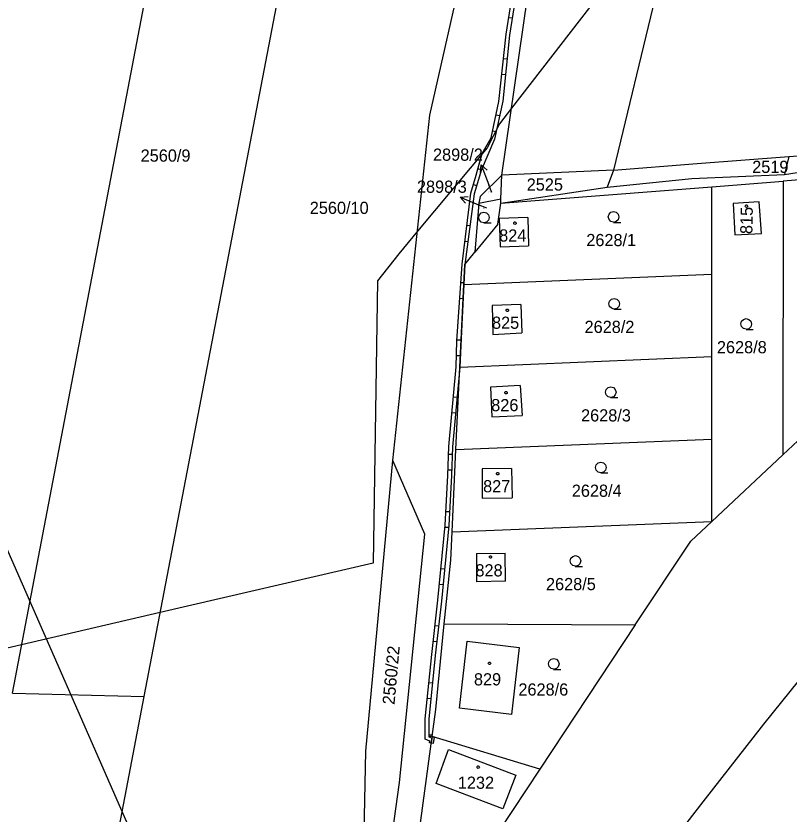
# Model space of a CAD drawing. Extents: x -760611 to -758411, y -1176479 to -1174807.
# Drawn here: x -759476.2 to -759368.4, y -1175293 to -1175181.7 of the extents above; entities that cross this region are included whole.
import ezdxf

# ---------------------------------------------------------------- set-up
doc = ezdxf.new("R2010")
doc.units = 0
for name, color, linetype in [('1', 7, 'Continuous'), ('11', 7, 'Continuous'), ('12', 7, 'Continuous'), ('13', 7, 'Continuous'), ('2', 7, 'Continuous'), ('3', 7, 'Continuous'), ('5', 7, 'Continuous'), ('6', 7, 'Continuous'), ('7', 7, 'Continuous')]:
    doc.layers.add(name, color=color, linetype=linetype)

msp = doc.modelspace()

# ---------------------------------------------------------------- linework, layer by layer
at = {"layer": '1'}
for p, q in [((-759370.78, -1175111.37), (-759392.87, -1175203.23)), ((-759458.35, -1175276.62), (-759430.62, -1175131.87)), ((-759476.73, -1175276.15), (-759451.36, -1175143.73)), ((-759408.44, -1175203.92), (-759400.15, -1175145.98)), ((-759418.48, -1175195.58), (-759410.58, -1175160.57)), ((-759423.64, -1175243.71), (-759418.48, -1175195.58)), ((-759369.05, -1175203.82), (-759338.17, -1175199.04)), ((-759368.43, -1175201.33), (-759365.05, -1175201.07)), ((-759381.2, -1175202.32), (-759368.43, -1175201.33)), ((-759368.43, -1175201.33), (-759369.05, -1175203.82)), ((-759392.87, -1175203.23), (-759408.44, -1175203.92)), ((-759392.87, -1175203.23), (-759393.78, -1175205.6)), ((-759392.87, -1175203.23), (-759381.2, -1175202.32)), ((-759408.44, -1175203.92), (-759411.49, -1175206.9)), ((-759408.58, -1175207.25), (-759408.44, -1175203.92)), ((-759393.78, -1175205.6), (-759381.97, -1175204.4)), ((-759381.97, -1175204.4), (-759369.05, -1175203.82)), ((-759357.27, -1175203.83), (-759369.21, -1175204.76)), ((-759408.6, -1175207.83), (-759379.17, -1175205.54)), ((-759379.17, -1175205.54), (-759369.21, -1175204.76)), ((-759379.17, -1175217.73), (-759379.17, -1175205.54)), ((-759369.21, -1175204.76), (-759369.26, -1175242.94)), ((-759408.6, -1175207.83), (-759393.78, -1175205.6)), ((-759411.49, -1175206.9), (-759411.65, -1175207.82)), ((-759411.65, -1175207.82), (-759408.58, -1175207.25)), ((-759408.6, -1175207.83), (-759408.58, -1175207.25)), ((-759372.56, -1175207.63), (-759376.17, -1175207.89)), ((-759372.24, -1175212.08), (-759372.56, -1175207.63)), ((-759411.65, -1175207.82), (-759412.21, -1175214.67)), ((-759409, -1175210.75), (-759408.6, -1175207.83)), ((-759376.17, -1175207.89), (-759375.96, -1175212.24)), ((-759404.85, -1175209.84), (-759408.82, -1175209.97)), ((-759408.82, -1175209.97), (-759408.68, -1175213.93)), ((-759404.85, -1175209.84), (-759404.72, -1175213.8)), ((-759409, -1175210.75), (-759412.21, -1175214.67)), ((-759375.96, -1175212.24), (-759372.24, -1175212.08)), ((-759408.68, -1175213.93), (-759404.72, -1175213.8)), ((-759413.64, -1175216.41), (-759412.21, -1175214.67)), ((-759413.77, -1175219.2), (-759413.64, -1175216.41)), ((-759413.77, -1175219.2), (-759379.17, -1175217.73)), ((-759379.18, -1175229.23), (-759379.17, -1175217.73)), ((-759414.32, -1175230.69), (-759413.77, -1175219.2)), ((-759405.83, -1175221.97), (-759409.79, -1175222.12)), ((-759409.79, -1175222.12), (-759409.71, -1175226.13)), ((-759405.83, -1175221.97), (-759405.68, -1175225.92)), ((-759409.71, -1175226.13), (-759405.68, -1175225.92)), ((-759414.32, -1175230.69), (-759379.18, -1175229.23)), ((-759379.18, -1175240.73), (-759379.18, -1175229.23)), ((-759414.86, -1175242.17), (-759414.32, -1175230.69)), ((-759357.28, -1175231.73), (-759369.26, -1175242.94)), ((-759405.89, -1175233.26), (-759410.05, -1175233.52)), ((-759405.89, -1175233.26), (-759405.64, -1175237.45)), ((-759410.05, -1175233.52), (-759409.87, -1175237.65)), ((-759409.87, -1175237.65), (-759405.64, -1175237.45)), ((-759414.86, -1175242.17), (-759379.18, -1175240.73)), ((-759379.19, -1175252.23), (-759379.18, -1175240.73)), ((-759415.4, -1175253.65), (-759414.86, -1175242.17)), ((-759369.26, -1175242.94), (-759379.19, -1175252.23)), ((-759427.43, -1175284.24), (-759423.64, -1175243.71)), ((-759419.22, -1175253.98), (-759423.64, -1175243.71)), ((-759407.11, -1175244.83), (-759411.22, -1175244.91)), ((-759411.22, -1175244.91), (-759411.21, -1175248.99)), ((-759407.11, -1175244.83), (-759407.02, -1175248.91)), ((-759411.21, -1175248.99), (-759407.02, -1175248.91)), ((-759415.4, -1175253.65), (-759379.19, -1175252.23)), ((-759379.19, -1175252.23), (-759382.11, -1175254.96)), ((-759422.71, -1175288.64), (-759419.22, -1175253.98)), ((-759415.59, -1175257.64), (-759415.4, -1175253.65)), ((-759389.84, -1175266.63), (-759382.11, -1175254.96)), ((-759411.98, -1175256.7), (-759412, -1175260.63)), ((-759411.98, -1175256.7), (-759407.99, -1175256.65)), ((-759407.97, -1175260.54), (-759407.99, -1175256.65)), ((-759416.48, -1175266.49), (-759415.59, -1175257.64)), ((-759407.97, -1175260.54), (-759412, -1175260.63)), ((-759417.68, -1175278.43), (-759416.48, -1175266.49)), ((-759416.48, -1175266.49), (-759389.84, -1175266.63)), ((-759389.84, -1175266.63), (-759403.18, -1175286.77)), ((-759414.38, -1175278.27), (-759413.28, -1175268.93)), ((-759413.28, -1175268.93), (-759406.02, -1175269.81)), ((-759406.02, -1175269.81), (-759407.12, -1175279.13)), ((-759476.73, -1175276.15), (-759458.35, -1175276.62)), ((-759463.25, -1175302.25), (-759458.35, -1175276.62)), ((-759418.19, -1175282.22), (-759417.68, -1175278.43)), ((-759407.12, -1175279.13), (-759414.38, -1175278.27)), ((-759422.12, -1175311.42), (-759418.19, -1175282.22)), ((-759403.18, -1175286.77), (-759418.19, -1175282.22)), ((-759427.83, -1175303.15), (-759427.43, -1175284.24)), ((-759417.64, -1175288.75), (-759415.88, -1175284.03)), ((-759415.88, -1175284.03), (-759406.51, -1175287.61)), ((-759403.18, -1175286.77), (-759408.89, -1175295.4)), ((-759406.51, -1175287.61), (-759408.32, -1175292.3)), ((-759424.83, -1175303.24), (-759422.71, -1175288.64)), ((-759408.32, -1175292.3), (-759417.64, -1175288.75))]:
    msp.add_line(p, q, dxfattribs=at)
at = {"layer": '11'}
msp.add_lwpolyline([(-759387.91, -1175169.78), (-759407.11, -1175194.59), (-759408.78, -1175196.76), (-759410.49, -1175200.14), (-759420.21, -1175211.75), (-759422.84, -1175214.88), (-759425.82, -1175218.68), (-759426.39, -1175258.03), (-759456.11, -1175264.92), (-759475.44, -1175269.41), (-759487.07, -1175272.11)], dxfattribs=at)
at = {"layer": '12'}
for p, q in [((-759372.56, -1175207.63), (-759376.17, -1175207.89)), ((-759372.24, -1175212.08), (-759372.56, -1175207.63)), ((-759376.17, -1175207.89), (-759375.96, -1175212.24)), ((-759404.85, -1175209.84), (-759408.82, -1175209.97)), ((-759408.82, -1175209.97), (-759408.68, -1175213.93)), ((-759404.85, -1175209.84), (-759404.72, -1175213.8)), ((-759375.96, -1175212.24), (-759372.24, -1175212.08)), ((-759408.68, -1175213.93), (-759404.72, -1175213.8)), ((-759405.83, -1175221.97), (-759409.79, -1175222.12)), ((-759409.79, -1175222.12), (-759409.71, -1175226.13)), ((-759405.83, -1175221.97), (-759405.68, -1175225.92)), ((-759409.71, -1175226.13), (-759405.68, -1175225.92)), ((-759405.89, -1175233.26), (-759410.05, -1175233.52)), ((-759405.89, -1175233.26), (-759405.64, -1175237.45)), ((-759410.05, -1175233.52), (-759409.87, -1175237.65)), ((-759409.87, -1175237.65), (-759405.64, -1175237.45)), ((-759407.11, -1175244.83), (-759411.22, -1175244.91)), ((-759411.22, -1175244.91), (-759411.21, -1175248.99)), ((-759407.11, -1175244.83), (-759407.02, -1175248.91)), ((-759411.21, -1175248.99), (-759407.02, -1175248.91)), ((-759411.98, -1175256.7), (-759412, -1175260.63)), ((-759411.98, -1175256.7), (-759407.99, -1175256.65)), ((-759407.97, -1175260.54), (-759407.99, -1175256.65)), ((-759407.97, -1175260.54), (-759412, -1175260.63)), ((-759414.38, -1175278.27), (-759413.28, -1175268.93)), ((-759413.28, -1175268.93), (-759406.02, -1175269.81)), ((-759406.02, -1175269.81), (-759407.12, -1175279.13)), ((-759407.12, -1175279.13), (-759414.38, -1175278.27)), ((-759417.64, -1175288.75), (-759415.88, -1175284.03)), ((-759415.88, -1175284.03), (-759406.51, -1175287.61)), ((-759406.51, -1175287.61), (-759408.32, -1175292.3)), ((-759408.32, -1175292.3), (-759417.64, -1175288.75))]:
    msp.add_line(p, q, dxfattribs=at)
at = {"layer": '13'}
for p, q in [((-759407.5, -1175181.92), (-759407, -1175182)), ((-759407.72, -1175187.74), (-759408.22, -1175187.69)), ((-759408.46, -1175189.86), (-759407.96, -1175189.91)), ((-759408.78, -1175195.66), (-759409.27, -1175195.55)), ((-759409.75, -1175197.74), (-759409.26, -1175197.85)), ((-759411.33, -1175203.2), (-759411.81, -1175203.07)), ((-759412.44, -1175205.22), (-759411.96, -1175205.36)), ((-759412.91, -1175211.02), (-759413.41, -1175210.96)), ((-759413.59, -1175213.12), (-759413.1, -1175213.18)), ((-759413.76, -1175218.97), (-759414.26, -1175218.95)), ((-759414.31, -1175221.09), (-759413.81, -1175221.12)), ((-759414.14, -1175226.96), (-759414.64, -1175226.94)), ((-759414.78, -1175229.07), (-759414.28, -1175229.09)), ((-759414.71, -1175234.94), (-759415.21, -1175234.89)), ((-759415.41, -1175237.05), (-759414.92, -1175237.09)), ((-759415.38, -1175242.91), (-759415.88, -1175242.9)), ((-759415.95, -1175245.02), (-759415.45, -1175245.04)), ((-759415.76, -1175250.9), (-759416.26, -1175250.87)), ((-759416.39, -1175253.01), (-759415.89, -1175253.04)), ((-759416.46, -1175258.87), (-759416.95, -1175258.82)), ((-759417.16, -1175260.97), (-759416.66, -1175261.02)), ((-759417.28, -1175266.83), (-759417.78, -1175266.77)), ((-759418.03, -1175268.93), (-759417.53, -1175268.98)), ((-759418.15, -1175274.78), (-759418.64, -1175274.73)), ((-759418.87, -1175276.88), (-759418.37, -1175276.93)), ((-759418.17, -1175282.03), (-759418.66, -1175281.97)), ((-759418.31, -1175283.14), (-759418.19, -1175282.22)), ((-759418.19, -1175282.22), (-759417.91, -1175282.3)), ((-759417.91, -1175282.3), (-759418.03, -1175283.18)), ((-759418.03, -1175283.18), (-759418.31, -1175283.14))]:
    msp.add_line(p, q, dxfattribs=at)
msp.add_lwpolyline([(-759405.3, -1175171.21), (-759407.37, -1175184.4), (-759408.34, -1175193.63), (-759409.5, -1175198.93), (-759411.36, -1175203.3), (-759411.58, -1175204.08), (-759412.3, -1175206.53), (-759413.64, -1175216.41), (-759414.04, -1175224.78), (-759414.32, -1175230.69), (-759415.35, -1175241.84), (-759415.47, -1175245.82), (-759415.87, -1175252.8), (-759416.89, -1175263.35), (-759417.75, -1175270.92), (-759418.66, -1175279.8), (-759418.63, -1175282.26), (-759418.42, -1175282.35), (-759418.39, -1175282.12), (-759418.19, -1175282.22), (-759418.31, -1175283.14), (-759418.53, -1175283.11), (-759418.5, -1175282.87), (-759419.13, -1175282.6), (-759419.16, -1175279.75), (-759418.24, -1175270.77), (-759417.37, -1175263.19), (-759416.37, -1175252.74), (-759415.97, -1175245.8), (-759415.85, -1175241.76), (-759414.82, -1175230.64), (-759414.73, -1175227.02), (-759413.98, -1175216.36), (-759412.8, -1175206.45), (-759412.06, -1175203.94), (-759411.86, -1175203.24), (-759411.18, -1175200.92), (-759409.96, -1175198.71), (-759408.86, -1175193.67), (-759407.87, -1175184.28), (-759405.78, -1175171.03)], dxfattribs=at)
at = {"layer": '3'}
for points in [[(-759410.94, -1175210.58), (-759411.32, -1175210.48), (-759411.59, -1175210.21), (-759411.69, -1175209.84), (-759411.59, -1175209.47), (-759411.32, -1175209.2), (-759410.95, -1175209.1), (-759410.58, -1175209.2), (-759410.31, -1175209.47), (-759410.21, -1175209.85), (-759410.31, -1175210.23), (-759410.58, -1175210.5), (-759410.96, -1175210.6), (-759409.96, -1175210.6)], [(-759392.86, -1175210.49), (-759393.24, -1175210.39), (-759393.51, -1175210.12), (-759393.61, -1175209.75), (-759393.51, -1175209.38), (-759393.24, -1175209.11), (-759392.87, -1175209.01), (-759392.5, -1175209.11), (-759392.23, -1175209.38), (-759392.13, -1175209.76), (-759392.23, -1175210.14), (-759392.5, -1175210.41), (-759392.88, -1175210.51), (-759391.88, -1175210.51)], [(-759392.78, -1175222.6), (-759393.16, -1175222.5), (-759393.43, -1175222.23), (-759393.53, -1175221.86), (-759393.43, -1175221.49), (-759393.16, -1175221.22), (-759392.79, -1175221.12), (-759392.42, -1175221.22), (-759392.15, -1175221.49), (-759392.05, -1175221.87), (-759392.15, -1175222.25), (-759392.42, -1175222.52), (-759392.8, -1175222.62), (-759391.8, -1175222.62)], [(-759374.37, -1175225.42), (-759374.75, -1175225.32), (-759375.02, -1175225.05), (-759375.12, -1175224.68), (-759375.02, -1175224.31), (-759374.75, -1175224.04), (-759374.38, -1175223.94), (-759374.01, -1175224.04), (-759373.74, -1175224.31), (-759373.64, -1175224.69), (-759373.74, -1175225.07), (-759374.01, -1175225.34), (-759374.39, -1175225.44), (-759373.39, -1175225.44)], [(-759393.26, -1175234.93), (-759393.64, -1175234.83), (-759393.91, -1175234.56), (-759394.01, -1175234.19), (-759393.91, -1175233.82), (-759393.64, -1175233.55), (-759393.27, -1175233.45), (-759392.9, -1175233.55), (-759392.63, -1175233.82), (-759392.53, -1175234.2), (-759392.63, -1175234.58), (-759392.9, -1175234.85), (-759393.28, -1175234.95), (-759392.28, -1175234.95)], [(-759394.64, -1175245.44), (-759395.02, -1175245.34), (-759395.29, -1175245.07), (-759395.39, -1175244.7), (-759395.29, -1175244.33), (-759395.02, -1175244.06), (-759394.65, -1175243.96), (-759394.28, -1175244.06), (-759394.01, -1175244.33), (-759393.91, -1175244.71), (-759394.01, -1175245.09), (-759394.28, -1175245.36), (-759394.66, -1175245.46), (-759393.66, -1175245.46)], [(-759398.19, -1175258.47), (-759398.57, -1175258.37), (-759398.84, -1175258.1), (-759398.94, -1175257.73), (-759398.84, -1175257.36), (-759398.57, -1175257.09), (-759398.2, -1175256.99), (-759397.83, -1175257.09), (-759397.56, -1175257.36), (-759397.46, -1175257.74), (-759397.56, -1175258.12), (-759397.83, -1175258.39), (-759398.21, -1175258.49), (-759397.21, -1175258.49)], [(-759401.21, -1175272.83), (-759401.59, -1175272.73), (-759401.86, -1175272.46), (-759401.96, -1175272.09), (-759401.86, -1175271.72), (-759401.59, -1175271.45), (-759401.22, -1175271.35), (-759400.85, -1175271.45), (-759400.58, -1175271.72), (-759400.48, -1175272.1), (-759400.58, -1175272.48), (-759400.85, -1175272.75), (-759401.23, -1175272.85), (-759400.23, -1175272.85)]]:
    msp.add_lwpolyline(points, dxfattribs=at)
at = {"layer": '5'}
for points in [[(-759374.34, -1175208.08), (-759374.24, -1175208.1), (-759374.19, -1175208.19), (-759374.17, -1175208.25), (-759374.19, -1175208.34), (-759374.27, -1175208.41), (-759374.34, -1175208.42), (-759374.43, -1175208.39), (-759374.49, -1175208.33), (-759374.51, -1175208.25), (-759374.49, -1175208.16), (-759374.41, -1175208.09)], [(-759406.63, -1175210.45), (-759406.53, -1175210.47), (-759406.48, -1175210.56), (-759406.46, -1175210.62), (-759406.48, -1175210.71), (-759406.56, -1175210.78), (-759406.63, -1175210.79), (-759406.72, -1175210.76), (-759406.78, -1175210.7), (-759406.8, -1175210.62), (-759406.78, -1175210.53), (-759406.7, -1175210.46)], [(-759407.7, -1175222.6), (-759407.6, -1175222.62), (-759407.55, -1175222.71), (-759407.53, -1175222.77), (-759407.55, -1175222.86), (-759407.63, -1175222.93), (-759407.7, -1175222.94), (-759407.79, -1175222.91), (-759407.85, -1175222.85), (-759407.87, -1175222.77), (-759407.85, -1175222.68), (-759407.77, -1175222.61)], [(-759407.87, -1175234.1), (-759407.77, -1175234.12), (-759407.72, -1175234.21), (-759407.7, -1175234.27), (-759407.72, -1175234.36), (-759407.8, -1175234.43), (-759407.87, -1175234.44), (-759407.96, -1175234.41), (-759408.02, -1175234.35), (-759408.04, -1175234.27), (-759408.02, -1175234.18), (-759407.94, -1175234.11)], [(-759409.03, -1175245.4), (-759408.93, -1175245.42), (-759408.88, -1175245.51), (-759408.86, -1175245.57), (-759408.88, -1175245.66), (-759408.96, -1175245.73), (-759409.03, -1175245.74), (-759409.12, -1175245.71), (-759409.18, -1175245.65), (-759409.2, -1175245.57), (-759409.18, -1175245.48), (-759409.1, -1175245.41)], [(-759410.05, -1175257.01), (-759409.95, -1175257.03), (-759409.9, -1175257.12), (-759409.88, -1175257.18), (-759409.9, -1175257.27), (-759409.98, -1175257.34), (-759410.05, -1175257.35), (-759410.14, -1175257.32), (-759410.2, -1175257.26), (-759410.22, -1175257.18), (-759410.2, -1175257.09), (-759410.12, -1175257.02)], [(-759410.18, -1175271.84), (-759410.08, -1175271.86), (-759410.03, -1175271.95), (-759410.01, -1175272.01), (-759410.03, -1175272.1), (-759410.11, -1175272.17), (-759410.18, -1175272.18), (-759410.27, -1175272.15), (-759410.33, -1175272.09), (-759410.35, -1175272.01), (-759410.33, -1175271.92), (-759410.25, -1175271.85)], [(-759411.75, -1175286.32), (-759411.65, -1175286.34), (-759411.6, -1175286.43), (-759411.58, -1175286.49), (-759411.6, -1175286.58), (-759411.68, -1175286.65), (-759411.75, -1175286.66), (-759411.84, -1175286.63), (-759411.9, -1175286.57), (-759411.92, -1175286.49), (-759411.9, -1175286.4), (-759411.82, -1175286.33)]]:
    msp.add_lwpolyline(points, close=True, dxfattribs=at)
at = {"layer": '6'}
for p, q in [((-759403.75, -1175424.27), (-759478.28, -1175254.17)), ((-759363.2, -1175269.62), (-759371.95, -1175280.48)), ((-759371.95, -1175280.48), (-759380.41, -1175291.31)), ((-759380.41, -1175291.31), (-759393.68, -1175308.39))]:
    msp.add_line(p, q, dxfattribs=at)
at = {"layer": '7'}
for p, q in [((-759411.33, -1175202.47), (-759410.25, -1175205.27)), ((-759409.84, -1175206.33), (-759410.25, -1175205.27)), ((-759414.26, -1175206.99), (-759411.49, -1175208.15)), ((-759410.56, -1175208.54), (-759411.49, -1175208.15))]:
    msp.add_line(p, q, dxfattribs=at)
for points in [[(-759411.44, -1175203.58), (-759411.33, -1175202.47), (-759410.5, -1175203.22)], [(-759413.53, -1175207.84), (-759414.26, -1175206.99), (-759413.14, -1175206.92)]]:
    msp.add_lwpolyline(points, dxfattribs=at)

# ---------------------------------------------------------------- texts
at = {"layer": '2'}
for s, height, p in [('2560/9', 1.7, (-759458.84, -1175202.05)), ('2519', 1.7, (-759373.54, -1175203.62)), ('2525', 1.7, (-759404.99, -1175206.09)), ('2898/2', 0.1, (-759410.36, -1175206.33)), ('2560/10', 1.7, (-759435.25, -1175209.34)), ('2898/3', 0.1, (-759411.08, -1175208.54)), ('824', 1.7, (-759408.83, -1175213.19)), ('2628/1', 1.7, (-759396.68, -1175213.83)), ('825', 1.7, (-759409.83, -1175225.36)), ('2628/2', 1.7, (-759396.92, -1175225.94)), ('2628/8', 1.7, (-759378.46, -1175228.77)), ('826', 1.7, (-759409.94, -1175236.85)), ('2628/3', 1.7, (-759397.41, -1175238.28)), ('827', 1.7, (-759411.07, -1175248.16)), ('2628/4', 1.7, (-759398.7, -1175248.79)), ('828', 1.7, (-759412.14, -1175259.89)), ('2628/5', 1.7, (-759402.3, -1175261.81)), ('829', 1.7, (-759412.35, -1175275.09)), ('2628/6', 1.7, (-759406.15, -1175276.51)), ('1232', 1.7, (-759414.6, -1175289.51))]:
    msp.add_text(s, height=height, dxfattribs=at).set_placement(p)
for s, rotation, p in [('815', 88.8658, (-759373.52, -1175212.16)), ('2560/22', 84.7978, (-759423.43, -1175277.83))]:
    msp.add_text(s, height=1.7, rotation=rotation, dxfattribs=at).set_placement(p)
at = {"layer": '7'}
for s, p in [('2898/2', (-759418.06, -1175201.92)), ('2898/3', (-759420.3, -1175206.39))]:
    msp.add_text(s, height=1.7, dxfattribs=at).set_placement(p)

doc.saveas('drawing.dxf')
